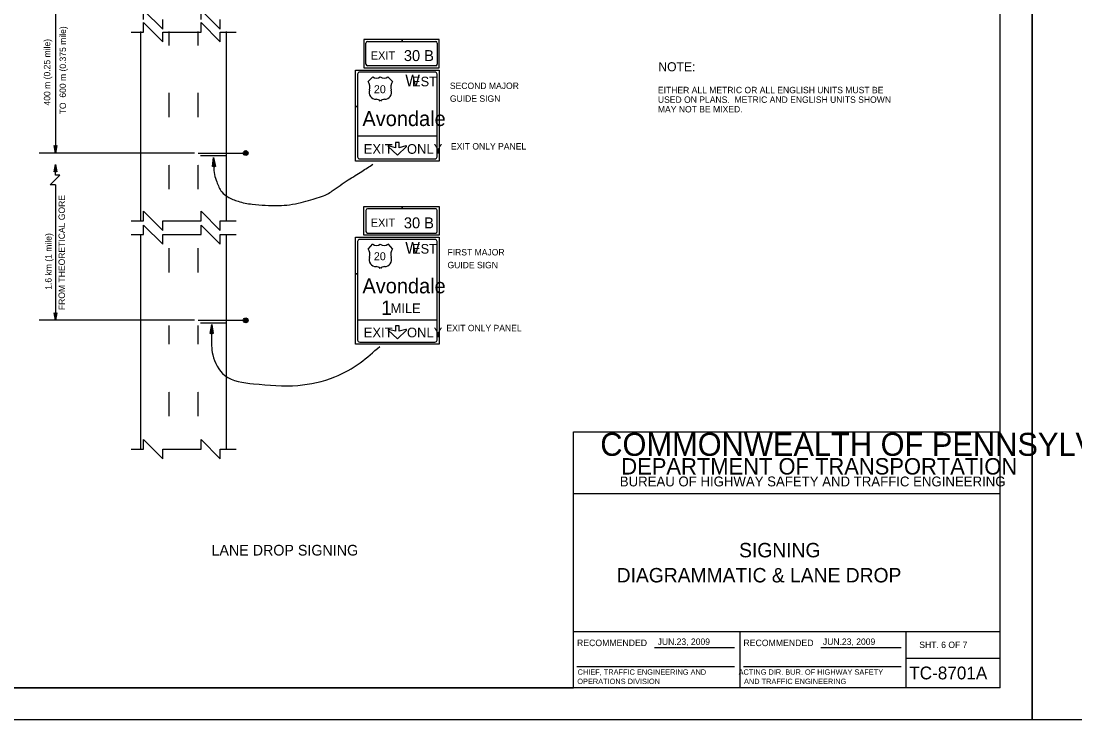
# Model space of a CAD drawing. Extents: x 640994 to 644422, y 298458 to 299646.
# Drawn here: x 642202.5 to 642696.3, y 298457.6 to 298785.1 of the extents above; entities that cross this region are included whole.
import ezdxf

# ---------------------------------------------------------------- set-up
doc = ezdxf.new("R2010")
doc.units = 0
for name, color, linetype in [('1', 7, 'Continuous'), ('2', 7, 'Continuous'), ('PLT-BNDY', 7, 'Continuous'), ('XCS-GRID-MIN', 7, 'Continuous')]:
    doc.layers.add(name, color=color, linetype=linetype)

msp = doc.modelspace()

# ---------------------------------------------------------------- linework, layer by layer
at = {"layer": '1'}
for p, q in [((642661.31, 298472.63), (642661.31, 299036.63)), ((642461.31, 298472.63), (642461.31, 298592.63)), ((642461.31, 298592.63), (642661.31, 298592.63)), ((642661.31, 298563.63), (642461.31, 298563.63)), ((642461.31, 298499), (642661.31, 298499)), ((642539.31, 298499), (642539.31, 298472.63)), ((642617.19, 298472.63), (642617.19, 298499)), ((642499.24, 298491.57), (642536.87, 298491.57)), ((642577.24, 298491.57), (642614.87, 298491.57)), ((642617.19, 298486.63), (642661.31, 298486.63)), ((642462.99, 298482.68), (642536.87, 298482.68)), ((642540.99, 298482.68), (642614.87, 298482.68)), ((642661.31, 298472.63), (641875.31, 298472.63)), ((641875.31, 298472.63), (642461.31, 298472.63))]:
    msp.add_line(p, q, dxfattribs=at)
at = {"layer": '2'}
for p, q in [((642218.56, 298821.75), (642218.56, 298723.25)), ((642254.06, 298779.88), (642259.94, 298779.88)), ((642258.56, 298691.5), (642258.56, 298780.13)), ((642268.94, 298779.88), (642286.81, 298779.88)), ((642271.94, 298773.63), (642271.94, 298780.13)), ((642285.44, 298773.63), (642285.44, 298780.13)), ((642295.81, 298779.88), (642303.31, 298779.88)), ((642298.81, 298691.5), (642298.81, 298780.13)), ((642271.94, 298773.63), (642271.94, 298773.63)), ((642285.44, 298773.63), (642285.44, 298773.63)), ((642381.12, 298776.5), (642363.06, 298776.5)), ((642363.06, 298776.5), (642363.06, 298763.13)), ((642364.06, 298764.88), (642364.06, 298774.75)), ((642364.81, 298775.5), (642381.12, 298775.5)), ((642381.12, 298775.5), (642381.12, 298776.5)), ((642398.44, 298776.5), (642381.12, 298776.5)), ((642381.12, 298776.5), (642381.12, 298775.5)), ((642381.12, 298775.5), (642396.81, 298775.5)), ((642397.44, 298774.75), (642397.44, 298764.88)), ((642398.44, 298763.13), (642398.44, 298776.5)), ((642363.06, 298763.13), (642398.44, 298763.13)), ((642396.81, 298764.13), (642364.81, 298764.13)), ((642359.19, 298745.06), (642359.19, 298762.13)), ((642359.19, 298762.13), (642398.44, 298762.13)), ((642360.19, 298760.13), (642360.19, 298745.06)), ((642396.44, 298761.13), (642361.19, 298761.13)), ((642365.19, 298756.75), (642367.31, 298758.88)), ((642374.31, 298758.88), (642376.56, 298756.75)), ((642397.44, 298721.5), (642397.44, 298760.13)), ((642398.44, 298762.13), (642398.44, 298719.5)), ((642271.94, 298751.38), (642271.94, 298751.38)), ((642271.94, 298740), (642271.94, 298751.38)), ((642285.44, 298751.38), (642285.44, 298751.38)), ((642285.44, 298740), (642285.44, 298751.38)), ((642368.81, 298748.38), (642368.81, 298748.38)), ((642370.81, 298753.13), (642370.81, 298753.13)), ((642370.81, 298753.13), (642370.81, 298753.13)), ((642370.81, 298753.13), (642370.81, 298753.13)), ((642370.81, 298753.13), (642370.81, 298753.13)), ((642370.81, 298753.13), (642370.81, 298753.13)), ((642372.94, 298748.38), (642372.94, 298748.38)), ((642373.06, 298751.13), (642373.06, 298751.13)), ((642376.06, 298751.75), (642376.06, 298751.75)), ((642360.19, 298745.06), (642359.19, 298745.06)), ((642359.19, 298719.5), (642359.19, 298745.06)), ((642359.19, 298745.06), (642360.19, 298745.06)), ((642360.19, 298745.06), (642360.19, 298721.5)), ((642271.94, 298740), (642271.94, 298740)), ((642285.44, 298740), (642285.44, 298740)), ((642378.69, 298739.38), (642378.69, 298739.38)), ((642218.56, 298723.25), (642217.94, 298726.75)), ((642217.94, 298726.75), (642218.19, 298726.63)), ((642218.44, 298726.5), (642218.19, 298726.63)), ((642218.19, 298726.63), (642218.56, 298723.25)), ((642218.56, 298723.25), (642218.44, 298726.5)), ((642219.19, 298726.75), (642218.56, 298723.25)), ((642218.56, 298723.25), (642219.06, 298726.63)), ((642218.81, 298726.5), (642218.56, 298723.25)), ((642219.06, 298726.63), (642218.81, 298726.5)), ((642219.06, 298726.63), (642219.19, 298726.75)), ((642306.81, 298723.13), (642307.94, 298724.25)), ((642308.56, 298723.75), (642306.81, 298723.13)), ((642307.94, 298724.25), (642306.94, 298723.75)), ((642307.06, 298722.63), (642307.06, 298723.75)), ((642307.06, 298723.75), (642307.44, 298722.5)), ((642307.44, 298722.5), (642307.56, 298724)), ((642307.56, 298724), (642307.94, 298722.38)), ((642307.69, 298722.38), (642308.56, 298723.75)), ((642307.94, 298722.38), (642307.94, 298724.25)), ((642307.94, 298724.25), (642308.31, 298722.5)), ((642308.31, 298722.5), (642308.31, 298724)), ((642308.31, 298724), (642308.56, 298723.13)), ((642374.44, 298726.25), (642378.81, 298722.25)), ((642377.94, 298725.75), (642374.69, 298726.63)), ((642379.69, 298728.25), (642377.94, 298728.25)), ((642378.81, 298722.25), (642383.06, 298726.25)), ((642382.81, 298726.63), (642379.69, 298725.75)), ((642283.81, 298723.25), (642210.94, 298723.25)), ((642285.44, 298723.25), (642307.81, 298723.25)), ((642286.56, 298722.13), (642298.81, 298722.13)), ((642308.56, 298723.13), (642307.69, 298722.38)), ((642307.81, 298723.25), (642307.81, 298723.25)), ((642398.44, 298719.5), (642359.19, 298719.5)), ((642361.19, 298720.5), (642396.44, 298720.5)), ((642217.94, 298714.42), (642218.57, 298717.92)), ((642218.07, 298714.54), (642217.94, 298714.42)), ((642218.57, 298717.92), (642218.07, 298714.54)), ((642218.07, 298714.54), (642218.32, 298714.67)), ((642218.32, 298714.67), (642218.57, 298717.92)), ((642218.57, 298717.92), (642218.69, 298714.67)), ((642218.94, 298714.54), (642218.57, 298717.92)), ((642218.57, 298717.92), (642219.19, 298714.42)), ((642218.69, 298714.67), (642218.94, 298714.54)), ((642219.19, 298714.42), (642218.94, 298714.54)), ((642271.94, 298717.75), (642271.94, 298717.75)), ((642271.94, 298717.63), (642271.94, 298717.63)), ((642271.94, 298706.25), (642271.94, 298717.63)), ((642285.44, 298717.75), (642285.44, 298717.75)), ((642285.44, 298717.63), (642285.44, 298717.63)), ((642285.44, 298706.25), (642285.44, 298717.63)), ((642218.56, 298708.38), (642218.56, 298644.88)), ((642271.94, 298706.38), (642271.94, 298706.38)), ((642271.94, 298706.25), (642271.94, 298706.25)), ((642285.44, 298706.38), (642285.44, 298706.38)), ((642285.44, 298706.25), (642285.44, 298706.25)), ((642363.06, 298684.75), (642363.06, 298698.13)), ((642363.06, 298698.13), (642381.12, 298698.13)), ((642364.06, 298696.38), (642364.06, 298686.5)), ((642381.12, 298697.13), (642364.81, 298697.13)), ((642381.12, 298698.13), (642381.12, 298697.13)), ((642381.12, 298697.13), (642381.12, 298698.13)), ((642381.12, 298698.13), (642398.44, 298698.13)), ((642396.81, 298697.13), (642381.12, 298697.13)), ((642397.44, 298686.5), (642397.44, 298696.38)), ((642398.44, 298698.13), (642398.44, 298684.75)), ((642254.06, 298691.5), (642259.94, 298691.5)), ((642268.94, 298691.5), (642286.81, 298691.5)), ((642295.81, 298691.5), (642303.31, 298691.5)), ((642254.06, 298685), (642259.94, 298685)), ((642258.56, 298584.25), (642258.56, 298685)), ((642268.94, 298685), (642286.81, 298685)), ((642295.81, 298685), (642303.31, 298685)), ((642298.81, 298584.25), (642298.81, 298685)), ((642398.44, 298684.75), (642363.06, 298684.75)), ((642364.81, 298685.75), (642396.81, 298685.75)), ((642359.19, 298683.75), (642398.44, 298683.75)), ((642396.44, 298682.75), (642361.19, 298682.75)), ((642365.19, 298678.25), (642367.31, 298680.63)), ((642374.31, 298680.63), (642376.56, 298678.25)), ((642397.44, 298635.63), (642397.44, 298681.75)), ((642398.44, 298683.75), (642398.44, 298633.63)), ((642271.94, 298678.63), (642271.94, 298678.63)), ((642271.94, 298667.25), (642271.94, 298678.63)), ((642285.44, 298678.63), (642285.44, 298678.63)), ((642285.44, 298667.25), (642285.44, 298678.63)), ((642370.81, 298674.88), (642370.81, 298674.88)), ((642370.81, 298674.88), (642370.81, 298674.88)), ((642370.81, 298674.88), (642370.81, 298674.88)), ((642370.81, 298674.88), (642370.81, 298674.88)), ((642368.81, 298670), (642368.81, 298670)), ((642372.94, 298670), (642372.94, 298670)), ((642373.06, 298672.63), (642373.06, 298672.63)), ((642376.06, 298673.25), (642376.06, 298673.25)), ((642271.94, 298667.25), (642271.94, 298667.25)), ((642285.44, 298667.25), (642285.44, 298667.25)), ((642360.19, 298666.65), (642359.19, 298666.65)), ((642359.19, 298666.65), (642360.19, 298666.65)), ((642283.81, 298644.88), (642210.94, 298644.88)), ((642218.56, 298644.88), (642217.94, 298648.38)), ((642217.94, 298648.38), (642218.19, 298648.25)), ((642218.44, 298648.13), (642218.19, 298648.25)), ((642218.19, 298648.25), (642218.56, 298644.88)), ((642218.56, 298644.88), (642218.44, 298648.13)), ((642219.19, 298648.38), (642218.56, 298644.88)), ((642218.56, 298644.88), (642219.06, 298648.25)), ((642218.81, 298648.13), (642218.56, 298644.88)), ((642219.06, 298648.25), (642218.81, 298648.13)), ((642219.06, 298648.25), (642219.19, 298648.38)), ((642271.94, 298645), (642271.94, 298645)), ((642285.44, 298645), (642285.44, 298645)), ((642285.44, 298644.88), (642307.81, 298644.88)), ((642306.81, 298644.63), (642307.94, 298645.75)), ((642308.56, 298645.38), (642306.81, 298644.63)), ((642307.94, 298645.75), (642306.94, 298645.5)), ((642307.06, 298644.25), (642307.06, 298645.25)), ((642307.06, 298645.25), (642307.44, 298644)), ((642307.44, 298644), (642307.56, 298645.63)), ((642307.56, 298645.63), (642307.94, 298643.88)), ((642307.69, 298643.88), (642308.56, 298645.38)), ((642308.56, 298644.75), (642307.69, 298643.88)), ((642307.81, 298644.88), (642307.81, 298644.88)), ((642307.94, 298643.88), (642307.94, 298645.75)), ((642307.94, 298645.75), (642308.31, 298644.13)), ((642308.31, 298644.13), (642308.31, 298645.63)), ((642308.31, 298645.63), (642308.56, 298644.75)), ((642360.19, 298645.13), (642397.44, 298645.13)), ((642271.94, 298633.75), (642271.94, 298642.38)), ((642285.44, 298633.75), (642285.44, 298642.38)), ((642286.56, 298643.75), (642298.81, 298643.75)), ((642374.44, 298640.25), (642378.81, 298636.25)), ((642377.94, 298639.75), (642374.69, 298640.63)), ((642379.69, 298642.25), (642377.94, 298642.25)), ((642378.81, 298636.25), (642383.06, 298640.25)), ((642382.81, 298640.63), (642379.69, 298639.75)), ((642271.94, 298633.75), (642271.94, 298633.75)), ((642285.44, 298633.75), (642285.44, 298633.75)), ((642398.44, 298633.63), (642359.19, 298633.63)), ((642361.19, 298634.63), (642396.44, 298634.63)), ((642271.94, 298611.38), (642271.94, 298611.38)), ((642271.94, 298611.25), (642271.94, 298611.25)), ((642271.94, 298599.88), (642271.94, 298611.25)), ((642285.44, 298611.38), (642285.44, 298611.38)), ((642285.44, 298611.25), (642285.44, 298611.25)), ((642285.44, 298599.88), (642285.44, 298611.25)), ((642271.94, 298600), (642271.94, 298600)), ((642271.94, 298599.88), (642271.94, 298599.88)), ((642285.44, 298600), (642285.44, 298600)), ((642285.44, 298599.88), (642285.44, 298599.88)), ((642254.06, 298584.5), (642259.94, 298584.5)), ((642258.56, 298584.25), (642258.56, 298584.25)), ((642268.94, 298584.5), (642286.81, 298584.5)), ((642295.81, 298584.5), (642303.31, 298584.5))]:
    msp.add_line(p, q, dxfattribs=at)
for points in [[(642259.94, 298785.75), (642259.94, 298790.25), (642268.94, 298781.25), (642268.94, 298785.75)], [(642286.81, 298785.75), (642286.81, 298790.25), (642295.81, 298781.25), (642295.81, 298785.75)], [(642259.94, 298779.88), (642259.94, 298784.38), (642268.94, 298775.38), (642268.94, 298779.88)], [(642286.81, 298779.88), (642286.81, 298784.38), (642295.81, 298775.38), (642295.81, 298779.88)], [(642360.19, 298731.25), (642397.44, 298731.25)], [(642377.94, 298728.25), (642377.94, 298725.75)], [(642379.69, 298725.75), (642379.69, 298728.25)], [(642292.31, 298717), (642292.56, 298717.13), (642292.69, 298721.13), (642292.31, 298717), (642292.19, 298716.88), (642292.69, 298721.13), (642292.94, 298717.13), (642293.31, 298717), (642292.69, 298721.13), (642293.56, 298716.88), (642293.31, 298717)], [(642218.57, 298708.38), (642216.19, 298708.38), (642220.69, 298712.88), (642218.57, 298712.88), (642218.57, 298717.92)], [(642259.94, 298691.5), (642259.94, 298696), (642268.94, 298687), (642268.94, 298691.5)], [(642286.81, 298691.5), (642286.81, 298696), (642295.81, 298687), (642295.81, 298691.5)], [(642259.94, 298685), (642259.94, 298689.5), (642268.94, 298680.5), (642268.94, 298685)], [(642286.81, 298685), (642286.81, 298689.5), (642295.81, 298680.5), (642295.81, 298685)], [(642359.19, 298666.65), (642359.19, 298683.75)], [(642360.19, 298681.75), (642360.19, 298666.65)], [(642359.19, 298633.63), (642359.19, 298666.65)], [(642360.19, 298666.65), (642360.19, 298635.63)], [(642291.19, 298638.75), (642291.56, 298638.88), (642291.94, 298642.88), (642291.19, 298638.75), (642291.06, 298638.63), (642291.94, 298642.88), (642291.94, 298638.88), (642292.31, 298638.75), (642291.94, 298642.88), (642292.44, 298638.63), (642292.31, 298638.75)], [(642377.94, 298642.25), (642377.94, 298639.75)], [(642379.69, 298639.75), (642379.69, 298642.25)], [(642259.94, 298584.5), (642259.94, 298589), (642268.94, 298580), (642268.94, 298584.5)], [(642286.81, 298584.5), (642286.81, 298589), (642295.81, 298580), (642295.81, 298584.5)]]:
    msp.add_lwpolyline(points, dxfattribs=at)
for centre in [(642307.75, 298723.24), (642307.75, 298644.86)]:
    msp.add_circle(centre, 1.12, dxfattribs=at)
for centre, radius, start, end in [((642361.19, 298760.13), 1, 90, 180), ((642369.08, 298761.24), 2.93, 233.136, 306.864), ((642372.59, 298761.24), 2.93, 233.136, 306.864), ((642396.44, 298760.13), 1, 0, 90), ((642361.41, 298754.14), 4.55, 341.8289, 34.5747), ((642380.25, 298754.14), 4.55, 145.4253, 198.1711), ((642368.83, 298751.69), 3.26, 161.452, 269.9953), ((642368.82, 298745.67), 2.76, 43.7275, 90), ((642372.84, 298745.67), 2.76, 90, 136.2725), ((642372.84, 298751.69), 3.26, 270.0047, 18.548), ((642374.66, 298726.4), 0.217, 75.9638, 226.9667), ((642382.88, 298726.4), 0.217, 313.0251, 104.0537), ((642361.19, 298721.5), 1, 180, 270), ((642396.44, 298721.5), 1, 270, 0), ((642361.19, 298681.75), 1, 90, 180), ((642369.08, 298682.86), 2.93, 233.136, 306.864), ((642372.59, 298682.86), 2.93, 233.136, 306.864), ((642396.44, 298681.75), 1, 0, 90), ((642361.41, 298675.76), 4.55, 341.8289, 34.5747), ((642368.83, 298673.3), 3.26, 161.452, 269.9953), ((642372.84, 298673.3), 3.26, 270.0047, 18.548), ((642380.25, 298675.76), 4.55, 145.4253, 198.1711), ((642368.82, 298667.28), 2.76, 43.7275, 90), ((642372.84, 298667.28), 2.76, 90, 136.2725), ((642374.66, 298640.4), 0.217, 75.9638, 226.9667), ((642382.88, 298640.4), 0.217, 313.0251, 104.0537), ((642361.19, 298635.63), 1, 180, 270), ((642396.44, 298635.63), 1, 270, 0)]:
    msp.add_arc(centre, radius, start, end, dxfattribs=at)
for centre, major_axis, start_param, end_param in [((642364.77, 298774.74), (0, -0.792), 3.141593, 4.712389), ((642396.8, 298774.74), (0, 0.792), 4.712389, 6.283185), ((642364.77, 298764.89), (0, -0.792), 4.712389, 6.283185), ((642396.8, 298764.89), (0, 0.792), 3.141593, 4.712389), ((642364.77, 298696.36), (0, -0.792), 3.141593, 4.712389), ((642396.8, 298696.36), (0, 0.792), 4.712389, 6.283185), ((642364.77, 298686.51), (0, -0.792), 4.712389, 6.283185), ((642396.8, 298686.51), (0, 0.792), 3.141593, 4.712389)]:
    msp.add_ellipse(centre, major_axis=major_axis, ratio=0.827467, start_param=start_param, end_param=end_param, dxfattribs=at)
for points in [[(642292.69, 298721.13), (642292.81, 298717), (642293.06, 298713.13), (642294.19, 298709.75), (642296.56, 298705), (642299.31, 298702.75), (642304.19, 298700.63), (642310.81, 298699.25), (642316.94, 298698.75), (642323.19, 298698.63), (642328.31, 298699), (642333.69, 298700.13), (642338.31, 298701.38), (642342.31, 298702.5), (642345.94, 298704), (642348.31, 298705.5), (642355.81, 298710.63), (642362.19, 298714.63), (642367.31, 298718)], [(642291.94, 298642.88), (642291.69, 298637.13), (642292.31, 298628.75), (642297.94, 298619), (642311.44, 298615.13), (642332.19, 298614.38), (642349.56, 298618.38), (642361.44, 298625), (642370.56, 298632.63)]]:
    msp.add_spline(points, degree=3, dxfattribs=at)
at = {"layer": 'XCS-GRID-MIN'}
for points in [[(641835.31, 299051.63), (642676.31, 299051.63), (642676.31, 298457.63), (641835.31, 298457.63)], [(642676.31, 299051.63), (643517.31, 299051.63), (643517.31, 298457.63), (642676.31, 298457.63)]]:
    msp.add_lwpolyline(points, close=True, dxfattribs=at)

# ---------------------------------------------------------------- texts
at = {"layer": '1'}
for s, height, p in [('COMMONWEALTH OF PENNSYLVANIA', 10.7828, (642473.9, 298581.36)), ('DEPARTMENT OF TRANSPORTATION', 7.6837, (642483.76, 298572.61)), ('BUREAU OF HIGHWAY SAFETY AND TRAFFIC ENGINEERING', 4.6253, (642483.04, 298567.04)), ('SIGNING', 6.75, (642538.96, 298533.81)), ('DIAGRAMMATIC & LANE DROP', 6.75, (642481.59, 298522.06)), ('RECOMMENDED', 3.048, (642462.99, 298492.2)), ('RECOMMENDED', 3.048, (642540.99, 298492.2)), ('SHT. 6 OF 7', 3, (642623.4, 298491.31)), ('TC-8701A', 6, (642618.68, 298476.63))]:
    msp.add_text(s, height=height, dxfattribs=at).set_placement(p)
at = {"layer": '2'}
for s, p in [('TO  600 m (0.375 mile)', (642223.54, 298741.38)), ('  400 m (0.25 mile) ', (642216.18, 298743.26)), ('FROM THEORETICAL GORE', (642223.04, 298649.64)), ('1.6 km (1 mile) ', (642216.8, 298659.16))]:
    msp.add_text(s, height=3, rotation=90, dxfattribs=at).set_placement(p)
for s, height, p in [('EXIT', 3.875, (642366.3, 298767.04)), ('30 B', 5.125, (642381.86, 298766.33)), ('NOTE:', 4.25, (642501.12, 298761.53)), ('W', 5.38, (642382.56, 298754.5)), ('EST', 4.5, (642385.69, 298754.5)), ('20', 3.75, (642367.81, 298751.25)), ('SECOND MAJOR', 3, (642403.44, 298753.25)), ('EITHER ALL METRIC OR ALL ENGLISH UNITS MUST BE', 3, (642500.9, 298751.26)), ('GUIDE SIGN', 3, (642403.44, 298747.25)), ('USED ON PLANS.  METRIC AND ENGLISH UNITS SHOWN', 3, (642500.9, 298746.76)), ('MAY NOT BE MIXED.', 3, (642500.9, 298742.26)), ('Avondale', 7, (642362.44, 298735.88)), ('EXIT    ONLY', 4.5457, (642363.06, 298722.88)), ('EXIT ONLY PANEL', 3, (642403.94, 298724.88)), ('EXIT', 3.875, (642366.3, 298688.67)), ('30 B', 5.125, (642381.86, 298687.95)), ('W', 5.38, (642382.56, 298676.13)), ('EST', 4.5, (642385.69, 298676.13)), ('20', 3.75, (642367.81, 298673)), ('FIRST MAJOR', 3, (642402.31, 298675.25)), ('GUIDE SIGN', 3, (642402.31, 298669.25)), ('Avondale', 7, (642362.44, 298657.5)), ('1', 6.75, (642371.19, 298647.38)), ('MILE', 4.5, (642375.69, 298648.25)), ('EXIT    ONLY', 4.5457, (642363.06, 298636.88)), ('EXIT ONLY PANEL', 3, (642401.81, 298639.75)), ('LANE DROP SIGNING', 5, (642291.71, 298534.65)), ('JUN.23, 2009', 3, (642500.78, 298492.78)), ('JUN.23, 2009', 3, (642578.23, 298492.78))]:
    msp.add_text(s, height=height, dxfattribs=at).set_placement(p)
at = {"layer": 'PLT-BNDY'}
for s, p in [('OPERATIONS DIVISION', (642463.14, 298474.44)), ('CHIEF, TRAFFIC ENGINEERING AND', (642463.28, 298478.81)), ('  ACTING DIR. BUR. OF HIGHWAY SAFETY', (642536.81, 298478.8)), ('  ACTING DIR. BUR. OF HIGHWAY SAFETY', (642536.81, 298478.8))]:
    msp.add_text(s, height=2.5, dxfattribs=at).set_placement(p)
msp.add_text('AND TRAFFIC ENGINEERING', height=2.5, rotation=360, dxfattribs=at).set_placement((642541.25, 298474.43))
msp.add_text('AND TRAFFIC ENGINEERING', height=2.5, rotation=360, dxfattribs=at).set_placement((642541.25, 298474.43))

doc.saveas('drawing.dxf')
